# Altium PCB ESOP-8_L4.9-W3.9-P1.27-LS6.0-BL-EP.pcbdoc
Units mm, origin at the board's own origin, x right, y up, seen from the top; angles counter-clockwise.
Board outline 18.45 x 19.72 mm, 2 copper layers (Top Layer, Bottom Layer), stack 0 mm thick; 1 components, 0 nets, 9 pads, 0 vias.
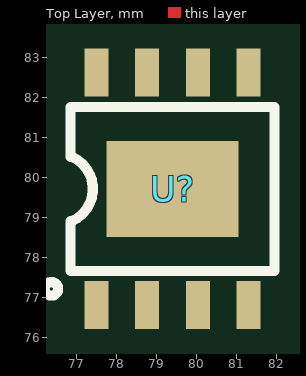
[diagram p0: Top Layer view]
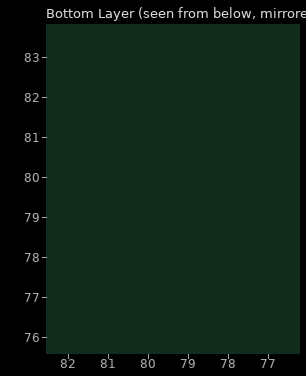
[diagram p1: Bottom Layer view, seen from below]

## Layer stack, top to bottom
Top Layer: signal copper (thickness not stored)
Bottom Layer: signal copper (thickness not stored)

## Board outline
88.3,69.85 69.85,69.85 69.85,89.567 88.3,89.567

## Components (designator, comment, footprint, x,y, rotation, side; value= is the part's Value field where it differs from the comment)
U? "" ESOP-8_L4.9-W3.9-P1.27-LS6.0-BL-EP 79.4,79.708 r0 top

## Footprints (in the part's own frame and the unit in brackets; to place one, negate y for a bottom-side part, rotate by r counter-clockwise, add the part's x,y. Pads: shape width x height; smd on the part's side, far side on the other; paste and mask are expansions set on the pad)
ESOP-8_L4.9-W3.9-P1.27-LS6.0-BL-EP [mm]
  rect 0.6x1.2 smd: 1(-1.905,-2.908) 2(-0.635,-2.908) 3(0.635,-2.908) 4(1.905,-2.908) 5(1.905,2.908) 6(0.635,2.908) 7(-0.635,2.908) 8(-1.905,2.908)
  rect 3.3x2.4 smd: 9(0,0)
  silkscreen extent -3.2,-2.67 2.55,2.05

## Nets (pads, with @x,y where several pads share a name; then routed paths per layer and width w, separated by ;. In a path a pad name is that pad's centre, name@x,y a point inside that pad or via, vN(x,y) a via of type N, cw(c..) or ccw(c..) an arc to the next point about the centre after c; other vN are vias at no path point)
pads on no net: U?.1 U?.2 U?.3 U?.4 U?.5 U?.6 U?.7 U?.8 U?.9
